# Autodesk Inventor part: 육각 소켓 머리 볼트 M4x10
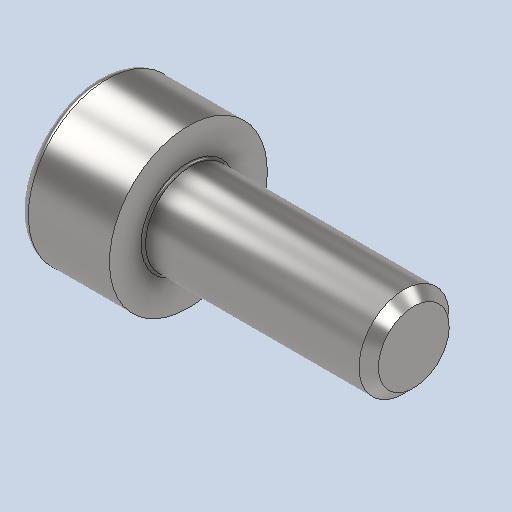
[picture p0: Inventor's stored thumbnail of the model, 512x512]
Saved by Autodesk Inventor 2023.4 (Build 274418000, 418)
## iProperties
Created: 2024-11
Part Number: 육각 소켓 머리 볼트 M4x10
Material: 강철, 연강
Description: 6각머리 태핑 나사
Document SubType Name: Modeling
Designer: EDU
Density: 7.85 g/cm^3
Appearance: 기본값
Author: jhkim
Sending System: Autodesk Inventor 2025
Preprocessor: ST-DEVELOPER v20
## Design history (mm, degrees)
feature "Solid1"
node "솔리드1"
